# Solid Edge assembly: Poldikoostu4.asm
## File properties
Author: Türk
Template: Iso Assembly.asm
Last saved by: Türk
Revision: 2
Application: Solid Edge
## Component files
Polt120x20.par
Mutter.par
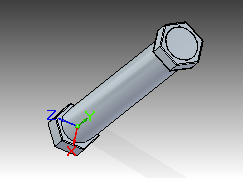
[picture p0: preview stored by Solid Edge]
